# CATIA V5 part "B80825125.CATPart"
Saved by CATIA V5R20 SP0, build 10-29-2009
Part number: B80825125
Revision: 3
Definition: design
Nomenclature: B80825125
Source: made
Description: NOT SPECIFIED
Bounding box of the stored display mesh (mm): x -15 to 15, y -15 to 15, z 0 to 125
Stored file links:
  C:\Users\Raffaele\Desktop\3D X SITO CF\BOLEX\4-PILLAR REF 808\B80825125.CATPart
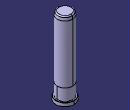
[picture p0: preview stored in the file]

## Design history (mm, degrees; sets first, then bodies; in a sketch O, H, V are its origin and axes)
Body1 "MANIFOLD_SOLID_BREP #450" (main body)
  Solid1: solid without history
